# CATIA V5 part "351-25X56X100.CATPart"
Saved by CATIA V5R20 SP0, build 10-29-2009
Part number: 351-25X56X100
Definition: NONE
Nomenclature: 351-25X56X100
Source: Unknown
Description: 351-25X56X100
Bounding box of the stored display mesh (mm): x -7 to 93, y -19 to 19, z -19 to 19
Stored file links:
  C:\Users\Utente\Desktop\IO LAVORO\3D X SITO CF\X SITO\PLASTICA\351\351-25X56X100.CATPart
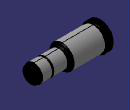
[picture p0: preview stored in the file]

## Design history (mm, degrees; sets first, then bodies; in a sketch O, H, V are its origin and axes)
Body1 "351-25X56X100" (main body)
  Solid1: solid without history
